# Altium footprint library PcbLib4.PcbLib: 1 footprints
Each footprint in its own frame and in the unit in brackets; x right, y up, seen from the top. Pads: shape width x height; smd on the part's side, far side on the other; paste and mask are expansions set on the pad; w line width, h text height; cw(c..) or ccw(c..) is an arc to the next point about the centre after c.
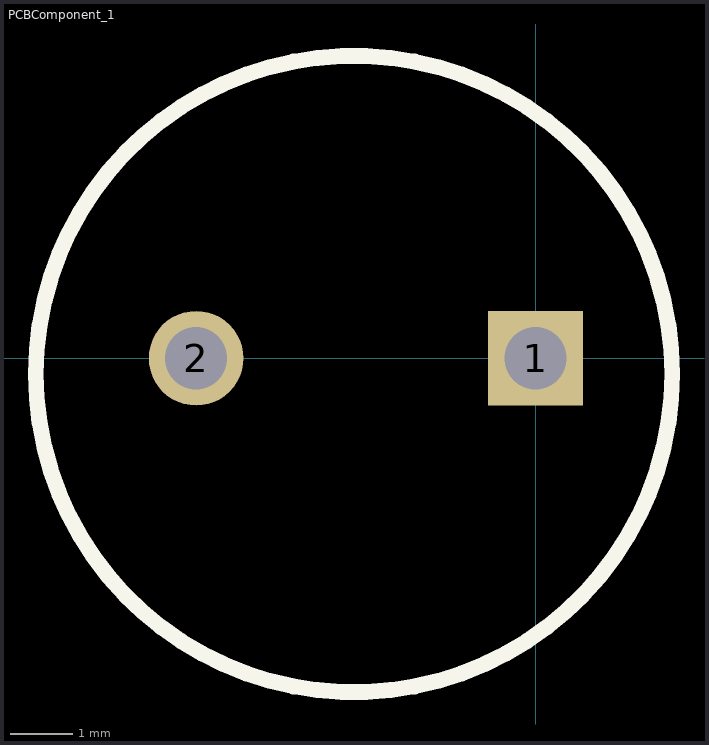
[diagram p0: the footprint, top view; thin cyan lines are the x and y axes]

## PCBComponent_1 [mil]
pads (2):
  rect 60x60 hole 39.37: 1(0,0)
  round 60 hole 39.37: 2(-215,0)
Top Overlay:
  circle w10: c-115,-10 r201.57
